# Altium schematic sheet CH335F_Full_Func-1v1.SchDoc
size 363 x 220 mm; PageSetup: Record=PageOptions¦CenterHorizontal=True¦CenterVertical=True¦PrintScale=0.65¦XCorrection=1.00¦YCorrection=1.00¦PrintKind=1¦BorderSize=5000000¦LeftOffset=0¦BottomOffset=0¦Orientation=2¦PaperLength=1000¦PaperWidth=1000¦Scale=100¦PaperSource=7¦PrintQuality=-4¦MediaType=1¦DitherType=10¦PaperKind=16 开 195x270¦PrintScaleMode=1
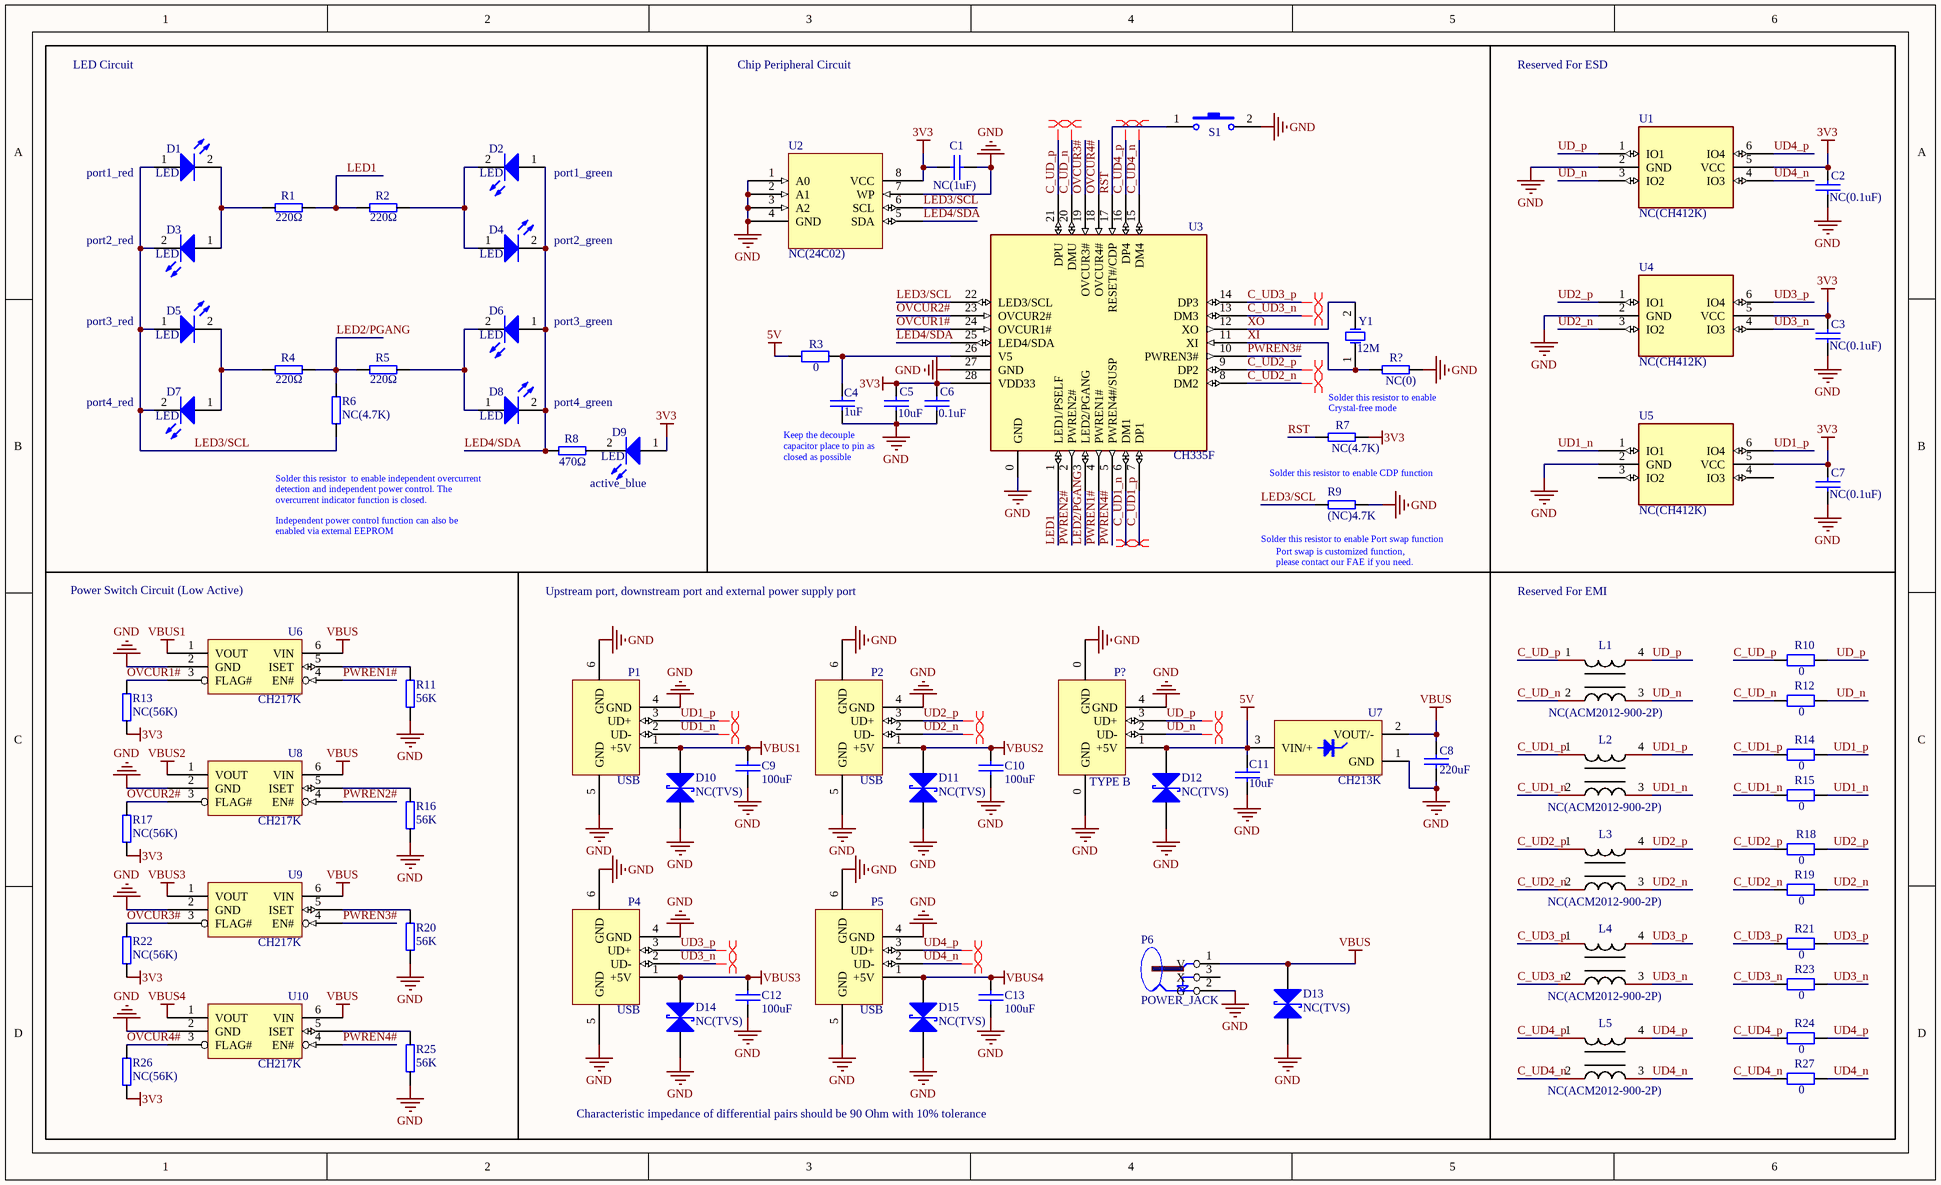
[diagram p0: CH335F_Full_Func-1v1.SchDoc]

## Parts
C1  NC(1uF)  [0603_C]
C2  NC(0.1uF)  [0603_C]
C3  NC(0.1uF)  [0603_C]
C4  1uF  [0603_C]
C5  10uF  [3216_C]
C6  0.1uF  [0603_C]
C7  NC(0.1uF)  [0603_C]
C8  220uF  [CAP-SMD_BD6.3-L6.6-W6.6-FD]
C9  100uF  [CAP-SMD_BD6.3-L6.6-W6.6-FD]
C10  100uF  [CAP-SMD_BD6.3-L6.6-W6.6-FD]
C11  10uF  [3216_C]
C12  100uF  [CAP-SMD_BD6.3-L6.6-W6.6-FD]
C13  100uF  [CAP-SMD_BD6.3-L6.6-W6.6-FD]
D1  LED  [0603+]
D2  LED  [0603+]
D3  LED  [0603+]
D4  LED  [0603+]
D5  LED  [0603+]
D6  LED  [0603+]
D7  LED  [0603+]
D8  LED  [0603+]
D9  LED  [0603+]
D10  NC(TVS)  [D0603-BI]
D11  NC(TVS)  [D0603-BI]
D12  NC(TVS)  [D0603-BI]
D13  NC(TVS)  [D0603-BI]
D14  NC(TVS)  [D0603-BI]
D15  NC(TVS)  [D0603-BI]
L1  NC(ACM2012-900-2P)  [IND-SMD_4P-L2.0-W1.2-TL]
L2  NC(ACM2012-900-2P)  [IND-SMD_4P-L2.0-W1.2-TL]
L3  NC(ACM2012-900-2P)  [IND-SMD_4P-L2.0-W1.2-TL]
L4  NC(ACM2012-900-2P)  [IND-SMD_4P-L2.0-W1.2-TL]
L5  NC(ACM2012-900-2P)  [IND-SMD_4P-L2.0-W1.2-TL]
P1  USB  [USBAF]
P2  USB  [USBAF]
P4  USB  [USBAF]
P5  USB  [USBAF]
P6  POWER_JACK  [DC-005]
P?  TYPE B  [USBB]
R1  220Ω  [0603_R]
R2  220Ω  [0603_R]
R3  0  [0603_R]
R4  220Ω  [0603_R]
R5  220Ω  [0603_R]
R6  NC(4.7K)  [0603_R]
R7  NC(4.7K)  [0603_R]
R8  470Ω  [0603_R]
R9  (NC)4.7K  [0603_R]
R10  0  [0603_R]
R11  56K  [0603_R]
R12  0  [0603_R]
R13  NC(56K)  [0603_R]
R14  0  [0603_R]
R15  0  [0603_R]
R16  56K  [0603_R]
R17  NC(56K)  [0603_R]
R18  0  [0603_R]
R19  0  [0603_R]
R20  56K  [0603_R]
R21  0  [0603_R]
R22  NC(56K)  [0603_R]
R23  0  [0603_R]
R24  0  [0603_R]
R25  56K  [0603_R]
R26  NC(56K)  [0603_R]
R27  0  [0603_R]
R?  NC(0)  [0603_R]
S1  (no value)  [SMD_6.1x3.65x2.5mm-KEY]
U1  NC(CH412K)  [SOT-363]
U2  NC(24C02)  [SOIC-8_150mil]
U3  CH335F  [QFN28_4X4]
U4  NC(CH412K)  [SOT-363]
U5  NC(CH412K)  [SOT-363]
U6  CH217K  [SOT-23-6]
U7  CH213K  [SOT-23-3]
U8  CH217K  [SOT-23-6]
U9  CH217K  [SOT-23-6]
U10  CH217K  [SOT-23-6]
Y1  12M  [XT_AT49]

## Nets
3V3: C1.1 C2.1 C3.1 C5.1 C6.1 C7.1 D9.1(A) R7.1 R13.1 R17.1 R22.1 R26.1 U1.5(VCC) U2.8(VCC) U3.28(VDD33) U4.5(VCC) U5.5(VCC)
5V: C11.1 D12.2(K) P?.1(+5V) R3.1 U7.3(VIN/+)
GND: C1.2 C2.2 C3.2 C4.2 C5.2 C6.2 C7.2 C8.2 C9.2 C10.2 C11.2 C12.2 C13.2 D10.1(A) D11.1(A) D12.1(A) D13.1(A) D14.1(A) D15.1(A) P1.4(GND) P1.5(GND) P1.6(GND) P2.4(GND) P2.5(GND) P2.6(GND) P4.4(GND) P4.5(GND) P4.6(GND) P5.4(GND) P5.5(GND) P5.6(GND) P6.2(G) P?.0(GND) P?.4(GND) R9.2 R11.1 R16.1 R20.1 R25.1 R?.1 S1.2 U1.2(GND) U2.1(A0) U2.2(A1) U2.3(A2) U2.4(GND) U2.7(WP) U3.0(GND) U3.27(GND) U4.2(GND) U5.2(GND) U6.2(GND) U7.1(GND) U8.2(GND) U9.2(GND) U10.2(GND)
VBUS: C8.1 D13.2(K) P6.1(V) U6.6(VIN) U7.2(VOUT/-) U8.6(VIN) U9.6(VIN) U10.6(VIN)
VBUS1: C9.1 D10.2(K) P1.1(+5V) U6.1(VOUT)
VBUS2: C10.1 D11.2(K) P2.1(+5V) U8.1(VOUT)
VBUS3: C12.1 D14.2(K) P4.1(+5V) U9.1(VOUT)
VBUS4: C13.1 D15.2(K) P5.1(+5V) U10.1(VOUT)
C_UD1_n: L2.2 R15.1 U3.6(DM1)
C_UD1_p: L2.1 R14.1 U3.7(DP1)
C_UD2_n: L3.2 R19.1 U3.8(DM2)
C_UD2_p: L3.1 R18.1 U3.9(DP2)
C_UD3_n: L4.2 R23.1 U3.13(DM3)
C_UD3_p: L4.1 R21.1 U3.14(DP3)
C_UD4_n: L5.2 R27.1 U3.15(DM4)
C_UD4_p: L5.1 R24.1 U3.16(DP4)
C_UD_n: L1.2 R12.1 U3.20(DMU)
C_UD_p: L1.1 R10.1 U3.21(DPU)
LED1: R1.2 R2.1 U3.1(LED1/PSELF)
LED2/PGANG: R4.2 R5.1 R6.1 U3.3(LED2/PGANG)
LED3/SCL: D1.1(A) D3.2(K) D5.1(A) D7.2(K) R6.2 R9.1 U2.6(SCL) U3.22(LED3/SCL)
LED4/SDA: D2.1(A) D4.2(K) D6.1(A) D8.2(K) R8.1 U2.5(SDA) U3.25(LED4/SDA)
OVCUR1#: R13.2 U3.24(OVCUR1#) U6.3(FLAG#)
OVCUR2#: R17.2 U3.23(OVCUR2#) U8.3(FLAG#)
OVCUR3#: R22.2 U3.19(OVCUR3#) U9.3(FLAG#)
OVCUR4#: R26.2 U3.18(OVCUR4#) U10.3(FLAG#)
PWREN1#: U3.4(PWREN1#) U6.4(EN#)
PWREN2#: U3.2(PWREN2#) U8.4(EN#)
PWREN3#: U3.10(PWREN3#) U9.4(EN#)
PWREN4#: U3.5(PWREN4#/SUSP) U10.4(EN#)
RST: R7.2 S1.1 U3.17(RESET#/CDP)
UD1_n: L2.3 P1.2(UD-) R15.2 U5.1(IO1)
UD1_p: L2.4 P1.3(UD+) R14.2 U5.6(IO4)
UD2_n: L3.3 P2.2(UD-) R19.2 U4.3(IO2)
UD2_p: L3.4 P2.3(UD+) R18.2 U4.1(IO1)
UD3_n: L4.3 P4.2(UD-) R23.2 U4.4(IO3)
UD3_p: L4.4 P4.3(UD+) R21.2 U4.6(IO4)
UD4_n: L5.3 P5.2(UD-) R27.2 U1.4(IO3)
UD4_p: L5.4 P5.3(UD+) R24.2 U1.6(IO4)
UD_n: L1.3 P?.2(UD-) R12.2 U1.3(IO2)
UD_p: L1.4 P?.3(UD+) R10.2 U1.1(IO1)
XI: R?.2 U3.11(XI) Y1.1(OSC1)
XO: U3.12(XO) Y1.2(OSC2)
NetC4_1: C4.1 R3.2 U3.26(V5)
NetD1_2: D1.2(K) D3.1(A) R1.1
NetD2_2: D2.2(K) D4.1(A) R2.2
NetD5_2: D5.2(K) D7.1(A) R4.1
NetD6_2: D6.2(K) D8.1(A) R5.2
NetD9_2: D9.2(K) R8.2
NetR11_2: R11.2 U6.5(ISET)
NetR16_2: R16.2 U8.5(ISET)
NetR20_2: R20.2 U9.5(ISET)
NetR25_2: R25.2 U10.5(ISET)

Not connected (* = marked no-connect by the designer): P6 3(X); U5 3(IO2) 4(IO3)

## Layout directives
differential pair: C_UD1_n, C_UD1_p, C_UD2_n, C_UD2_p, C_UD3_n, C_UD3_p, C_UD4_n, C_UD4_p, C_UD_n, C_UD_p, UD1_n, UD1_p, UD2_n, UD2_p, UD3_n, UD3_p, UD4_n, UD4_p, UD_n, UD_p

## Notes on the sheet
- LED Circuit
- Chip Peripheral Circuit
- Reserved For ESD
- (near D1) port1_red
- (near D2) port1_green
- (near D3) port2_red
- (near D4) port2_green
- (near D5) port3_red
- (near D6) port3_green
- (near D7) port4_red
- port4_green
- Keep the decouple capacitor place to pin as closed as possible
- Solder this resistor to enable Crystal-free mode
- Solder this resistor  to enable independent overcurrent detection and independent power control. The overcurrent indicator function is closed.
- active_blue
- Solder this resistor to enable CDP function
- Power Switch Circuit (Low Active)
- Independent power control function can also be enabled via external EEPROM
- Upstream port, downstream port and external power supply port
- (near R9) Solder this resistor to enable Port swap function
- (near R9) Port swap is customized function,
  please contact our FAE if you need.
- Reserved For EMI
- Characteristic impedance of differential pairs should be 90 Ohm with 10% tolerance

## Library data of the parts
C1-C13 = CAP: Capacitor
D1-D9 = LED: Typical INFRARED GaAs LED
D10-D15 = 双向TVS
L1-L5 = ACM2012-900-2P-T002: Manufacturer: TDK; Add into BOM: yes; Number of Lines: 2; Withstanding Voltage: 50V; Current Rating: 400mA; Impedance @ Frequency: 90Ω@100MHz; DC Resistance (DCR): 190mΩ
P1 P2 P4 P5 P? = USB: USB Port
R1 R2 R4-R9 R11 R13 R16 R17 R20 R22 R25 R26 R? = RES
R3 R10 R12 R14 R15 R18 R19 R21 R23 R24 R27 = R-High Precision: 贴片精密电阻
S1 = SW-PB: Switch
U1 U4 U5 = CH412K: Qaud ESD protect, high speed
U2 = 24C01
U3 = CH335F: 4 ports High-Speed USB MTT Hub with 4 over current detect & power control
U6 U8-U10 = CH217K: Current-Limited USB Power Distribution Switch
U7 = CH213K: Ideal Diode 5V*1A
Y1 = XTAL: Crystal Oscillator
